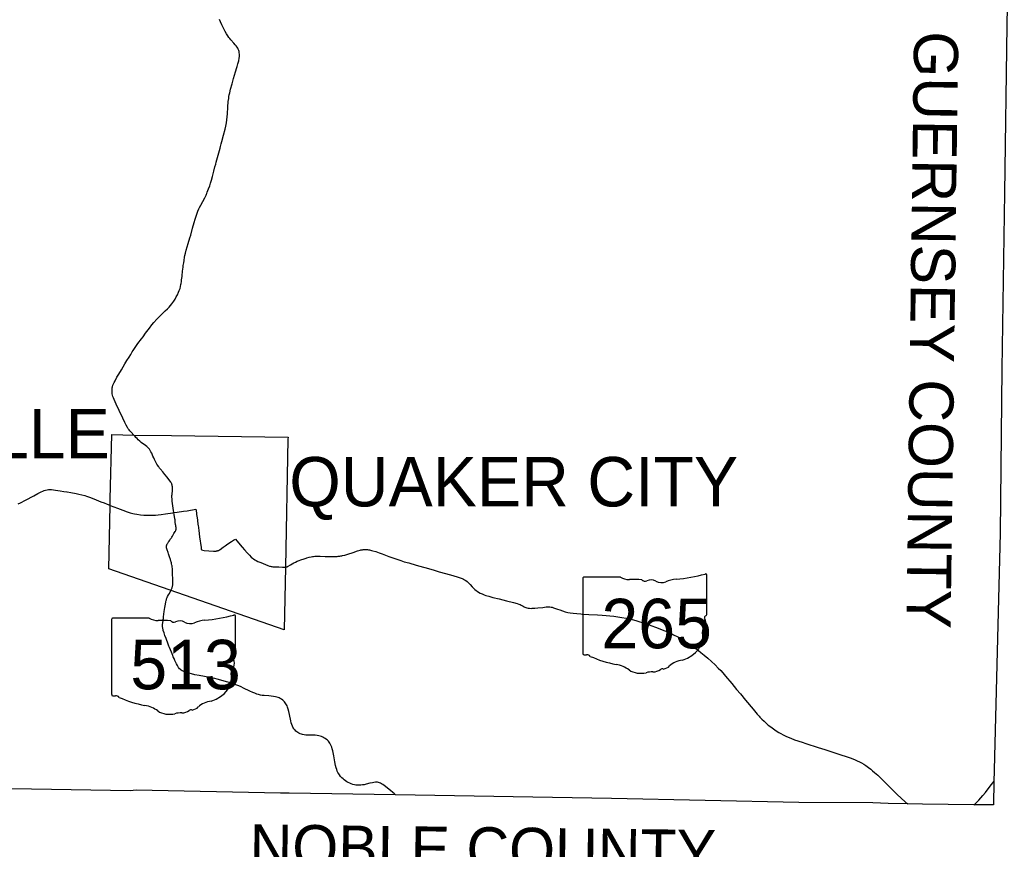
# Model space of a CAD drawing. Extents: x 2125567 to 2397567, y 653347 to 829347.
# Drawn here: x 2301307 to 2323667, y 712158 to 730931 of the extents above; entities that cross this region are included whole.
import ezdxf

# ---------------------------------------------------------------- set-up
doc = ezdxf.new("R2010")
doc.units = 0
for name, color, linetype in [('GM_X_Corporation', 7, 'Continuous'), ('GM_X_Corporation_Text', 7, 'Continuous'), ('GM_X_County', 7, 'Continuous'), ('GM_X_County_Text', 7, 'Continuous'), ('GM_X_State_Location', 7, 'Continuous'), ('GM_X_State_Route', 7, 'Continuous'), ('GM_X_State_Shield', 7, 'Continuous')]:
    doc.layers.add(name, color=color, linetype=linetype)

msp = doc.modelspace()

# ---------------------------------------------------------------- linework, layer by layer
at = {"layer": 'GM_X_Corporation'}
msp.add_lwpolyline([(2307286, 717126), (2303323, 718508), (2303355, 719937), (2303354, 720082), (2303390, 721541), (2303889, 721533), (2304739, 721520), (2307379, 721481), (2307373, 721436), (2307316, 718542)], close=True, dxfattribs=at)
at = {"layer": 'GM_X_County'}
msp.add_lwpolyline([(2323667, 732524), (2323636, 730805), (2323583, 727016), (2323525, 723028), (2323487, 719315), (2323348, 713955), (2323348, 713936), (2323344, 713702), (2323335, 713160), (2322891, 713164), (2321725, 713181), (2321394, 713182), (2320948, 713197), (2320605, 713210), (2318932, 713217), (2314694, 713310), (2309806, 713393), (2307398, 713424), (2307208, 713426), (2303943, 713494), (2303805, 713481), (2299787, 713549)], dxfattribs=at)
at = {"layer": 'GM_X_State_Route'}
msp.add_line((2305339, 719510), (2305342, 719489), dxfattribs=at)
for points in [[(2303890, 721530), (2303826, 721598), (2303799, 721627), (2303780, 721650), (2303763, 721674), (2303745, 721702), (2303716, 721754), (2303683, 721818), (2303635, 721915), (2303554, 722087), (2303488, 722230), (2303440, 722335), (2303425, 722371), (2303413, 722406), (2303405, 722438), (2303399, 722467), (2303396, 722500), (2303395, 722527), (2303396, 722560), (2303399, 722593), (2303401, 722603), (2303405, 722626), (2303414, 722658), (2303426, 722689), (2303439, 722719), (2303462, 722763), (2303505, 722840), (2303549, 722913), (2303609, 723011), (2303687, 723141), (2303733, 723216), (2303779, 723292), (2303819, 723359), (2303852, 723412), (2303873, 723445), (2303936, 723538), (2303981, 723602), (2304060, 723707), (2304097, 723757), (2304155, 723837), (2304243, 723955), (2304297, 724026), (2304341, 724079), (2304405, 724153), (2304446, 724196), (2304490, 724241), (2304597, 724342), (2304647, 724389), (2304684, 724427), (2304719, 724466), (2304748, 724501), (2304771, 724532), (2304792, 724562), (2304819, 724606), (2304848, 724657), (2304872, 724704), (2304899, 724763), (2304916, 724806), (2304932, 724852), (2304943, 724896), (2304952, 724937), (2304957, 724966), (2304963, 725005), (2304969, 725047), (2304974, 725086), (2304979, 725122), (2304984, 725164), (2304989, 725210), (2304992, 725236), (2304998, 725291), (2305002, 725324), (2305007, 725366), (2305017, 725428), (2305025, 725486), (2305036, 725561), (2305043, 725599), (2305054, 725647), (2305072, 725714), (2305118, 725868), (2305158, 725996), (2305176, 726059), (2305217, 726211), (2305256, 726344), (2305278, 726419), (2305304, 726507), (2305319, 726554), (2305336, 726600), (2305358, 726651), (2305373, 726683), (2305400, 726736), (2305446, 726819), (2305491, 726899), (2305523, 726963), (2305532, 726985), (2305538, 726999), (2305550, 727033), (2305579, 727103), (2305604, 727171), (2305624, 727233), (2305644, 727299), (2305666, 727384), (2305696, 727505), (2305723, 727603), (2305739, 727660), (2305752, 727711), (2305826, 727973), (2305841, 728026), (2305850, 728063), (2305865, 728127), (2305877, 728175), (2305916, 728318), (2305952, 728457), (2305967, 728521), (2305981, 728595), (2305992, 728666), (2306000, 728734), (2306006, 728806), (2306016, 728950), (2306025, 729084), (2306033, 729153), (2306038, 729192), (2306046, 729234), (2306056, 729279), (2306077, 729359), (2306112, 729485), (2306144, 729599), (2306166, 729677), (2306187, 729750), (2306194, 729772), (2306209, 729826), (2306222, 729873), (2306242, 729935), (2306260, 730005), (2306272, 730062), (2306277, 730098), (2306278, 730123), (2306277, 730136), (2306276, 730149), (2306273, 730181), (2306267, 730210), (2306259, 730238), (2306249, 730265), (2306237, 730288), (2306222, 730313), (2306204, 730340), (2306181, 730367), (2306149, 730404), (2306084, 730474), (2306059, 730504), (2306036, 730533), (2306012, 730568), (2305984, 730612), (2305954, 730664), (2305915, 730740), (2305877, 730820), (2305847, 730885), (2305826, 730937)], [(2304753, 720195), (2304756, 720217), (2304758, 720233), (2304759, 720247), (2304760, 720261), (2304762, 720279), (2304762, 720292), (2304763, 720310), (2304763, 720319), (2304763, 720331), (2304762, 720344), (2304762, 720352), (2304761, 720360), (2304761, 720365), (2304760, 720370), (2304759, 720374), (2304758, 720379), (2304757, 720387), (2304756, 720391), (2304755, 720396), (2304753, 720403), (2304753, 720407), (2304751, 720411), (2304750, 720415), (2304749, 720418), (2304748, 720422), (2304746, 720426), (2304738, 720444), (2304734, 720452), (2304725, 720469), (2304712, 720490), (2304682, 720530), (2304644, 720578), (2304591, 720641), (2304565, 720671), (2304542, 720698), (2304524, 720721), (2304511, 720736), (2304497, 720753), (2304487, 720765), (2304471, 720784), (2304451, 720810), (2304444, 720819), (2304428, 720843), (2304408, 720876), (2304400, 720891), (2304384, 720920), (2304369, 720952), (2304356, 720979), (2304339, 721013), (2304320, 721055), (2304310, 721079), (2304292, 721121), (2304274, 721156), (2304258, 721184), (2304239, 721211), (2304221, 721233), (2304203, 721251), (2304194, 721260), (2304180, 721272), (2304152, 721293), (2304120, 721315), (2304085, 721340), (2304057, 721362), (2304022, 721393), (2303989, 721425), (2303961, 721453), (2303936, 721479), (2303914, 721503), (2303890, 721530)], [(2301270, 719974), (2301323, 720001), (2301435, 720062), (2301622, 720158), (2301715, 720207), (2301793, 720247), (2301826, 720263), (2301856, 720274), (2301890, 720285), (2301928, 720294), (2301957, 720298), (2301979, 720299), (2302025, 720298), (2302074, 720293), (2302116, 720288), (2302221, 720271), (2302301, 720257), (2302373, 720245)], [(2302373, 720245), (2302379, 720244), (2302466, 720230), (2302586, 720209), (2302644, 720198), (2302714, 720181), (2302777, 720163), (2302817, 720151), (2302885, 720126), (2302986, 720087), (2303144, 720024), (2303214, 719997), (2303281, 719970), (2303343, 719944), (2303351, 719941)], [(2304753, 720086), (2304752, 720091), (2304751, 720100), (2304750, 720112), (2304750, 720124), (2304749, 720135), (2304749, 720146), (2304750, 720156), (2304750, 720162), (2304750, 720168), (2304751, 720179), (2304753, 720195)], [(2304832, 719511), (2304825, 719559), (2304819, 719611), (2304815, 719633), (2304801, 719731), (2304795, 719778), (2304787, 719828), (2304780, 719880), (2304758, 720039), (2304753, 720086)], [(2303351, 719941), (2303518, 719874), (2303638, 719830), (2303738, 719796), (2303807, 719774), (2303864, 719759), (2303906, 719750), (2303954, 719741), (2304042, 719729), (2304114, 719721), (2304177, 719718), (2304243, 719716), (2304264, 719717)], [(2304264, 719717), (2304308, 719717), (2304377, 719721), (2304440, 719727), (2304508, 719736), (2304605, 719750), (2304771, 719774), (2304795, 719778)], [(2304795, 719778), (2304865, 719785), (2305011, 719807), (2305092, 719818), (2305292, 719853)], [(2305292, 719853), (2305302, 719774), (2305308, 719733), (2305318, 719662), (2305326, 719604), (2305339, 719510)], [(2304684, 719133), (2304699, 719155), (2304717, 719182), (2304736, 719209), (2304746, 719224), (2304760, 719246), (2304778, 719274), (2304795, 719302), (2304822, 719346), (2304829, 719358), (2304834, 719369), (2304837, 719378), (2304840, 719386), (2304842, 719398), (2304843, 719406), (2304843, 719414), (2304843, 719418), (2304843, 719427), (2304842, 719440), (2304839, 719463), (2304836, 719485), (2304832, 719511)], [(2305342, 719489), (2305357, 719373), (2305376, 719230), (2305407, 718989), (2305408, 718982), (2305409, 718976), (2305410, 718968)], [(2304726, 718012), (2304742, 718047), (2304748, 718062), (2304752, 718075), (2304756, 718088), (2304760, 718102), (2304764, 718119), (2304767, 718137), (2304768, 718154), (2304769, 718169), (2304770, 718188), (2304770, 718205), (2304768, 718286), (2304764, 718378), (2304762, 718469), (2304759, 718512), (2304755, 718544), (2304751, 718572), (2304748, 718589), (2304743, 718618), (2304740, 718636), (2304737, 718646), (2304735, 718655), (2304734, 718661), (2304732, 718666), (2304727, 718680), (2304714, 718717), (2304693, 718779), (2304680, 718819), (2304672, 718844), (2304661, 718875), (2304654, 718896), (2304649, 718909), (2304633, 718956), (2304631, 718964), (2304629, 718972), (2304627, 718981), (2304626, 718991), (2304625, 718998), (2304625, 719005), (2304625, 719012), (2304625, 719019), (2304627, 719026), (2304630, 719035), (2304632, 719043), (2304637, 719053), (2304642, 719064), (2304647, 719075), (2304654, 719087), (2304662, 719101), (2304681, 719129), (2304684, 719133)], [(2305418, 718931), (2305479, 718921), (2305581, 718913), (2305689, 718906), (2305719, 718905), (2305732, 718906), (2305747, 718908), (2305760, 718910), (2305772, 718912), (2305781, 718915), (2305788, 718917), (2305797, 718920), (2305805, 718923), (2305825, 718934), (2305838, 718943), (2305908, 718992), (2305956, 719027), (2306017, 719071), (2306096, 719124), (2306140, 719152), (2306184, 719179)], [(2306184, 719179), (2306219, 719138), (2306341, 718997), (2306393, 718938), (2306453, 718869), (2306504, 718810), (2306542, 718771), (2306569, 718747), (2306594, 718728), (2306624, 718709), (2306658, 718690), (2306696, 718672), (2306759, 718645), (2306868, 718600), (2306919, 718579), (2306956, 718567), (2306973, 718563), (2306993, 718558), (2307012, 718555), (2307032, 718552), (2307056, 718550), (2307080, 718549), (2307165, 718546), (2307247, 718544), (2307289, 718544), (2307305, 718544), (2307312, 718544)], [(2305410, 718968), (2305412, 718958), (2305413, 718952), (2305415, 718942), (2305418, 718931)], [(2307312, 718544), (2307319, 718545), (2307330, 718546), (2307343, 718548), (2307354, 718552), (2307364, 718556), (2307373, 718560), (2307380, 718564), (2307434, 718596), (2307506, 718637), (2307541, 718655), (2307585, 718676), (2307625, 718692), (2307668, 718708), (2307737, 718730), (2307784, 718745), (2307799, 718750), (2307852, 718765), (2307900, 718778), (2307928, 718784), (2307955, 718787), (2307983, 718790), (2308014, 718791), (2308100, 718790), (2308212, 718787), (2308244, 718786), (2308303, 718785), (2308421, 718785), (2308486, 718787), (2308507, 718788), (2308528, 718790), (2308546, 718792), (2308570, 718796), (2308591, 718800), (2308611, 718804), (2308659, 718817), (2308731, 718838), (2308849, 718877), (2308949, 718909), (2309006, 718926), (2309026, 718931), (2309045, 718935), (2309059, 718938), (2309074, 718940), (2309085, 718942), (2309097, 718943), (2309112, 718944), (2309127, 718944), (2309139, 718944), (2309157, 718943), (2309173, 718941), (2309193, 718938), (2309217, 718933), (2309242, 718927), (2309266, 718922), (2309293, 718914), (2309362, 718894), (2309440, 718868), (2309505, 718844), (2309659, 718787), (2309680, 718779), (2309813, 718731), (2309930, 718690), (2310005, 718666), (2310106, 718637), (2310273, 718590), (2310440, 718541), (2310469, 718533), (2310658, 718479), (2310797, 718439), (2311048, 718365), (2311200, 718321), (2311269, 718299), (2311315, 718282), (2311346, 718269), (2311369, 718257), (2311395, 718242), (2311424, 718220), (2311454, 718193), (2311494, 718149), (2311538, 718100), (2311569, 718067), (2311603, 718036), (2311633, 718011), (2311651, 717998), (2311681, 717979), (2311721, 717957), (2311766, 717936), (2311811, 717918), (2311851, 717904), (2311917, 717884), (2312012, 717858), (2312155, 717823), (2312321, 717781), (2312473, 717741), (2312559, 717717), (2312596, 717706), (2312624, 717695), (2312651, 717682), (2312697, 717657), (2312719, 717645)], [(2309751, 713435), (2309743, 713441), (2309690, 713485), (2309628, 713539), (2309581, 713580), (2309550, 713604), (2309521, 713624), (2309493, 713641), (2309467, 713654), (2309443, 713664), (2309419, 713670), (2309396, 713673), (2309377, 713675), (2309351, 713674), (2309319, 713670), (2309284, 713664), (2309227, 713650), (2309144, 713629), (2309099, 713619), (2309057, 713613), (2309020, 713609), (2308987, 713608), (2308948, 713609), (2308912, 713612), (2308879, 713617), (2308840, 713626), (2308806, 713637), (2308772, 713651), (2308739, 713666), (2308708, 713684), (2308674, 713706), (2308645, 713728), (2308620, 713749), (2308592, 713777), (2308566, 713807), (2308540, 713840), (2308521, 713868), (2308505, 713896), (2308490, 713926), (2308476, 713963), (2308464, 714001), (2308452, 714052), (2308434, 714139), (2308409, 714271), (2308387, 714383), (2308375, 714431), (2308363, 714468), (2308350, 714501), (2308336, 714531), (2308320, 714559), (2308306, 714580), (2308289, 714601), (2308267, 714624), (2308243, 714645), (2308217, 714664), (2308189, 714682), (2308161, 714697), (2308134, 714709), (2308104, 714720), (2308072, 714728), (2308037, 714733), (2307992, 714737), (2307903, 714740), (2307808, 714741), (2307775, 714743), (2307739, 714748), (2307706, 714754), (2307678, 714762), (2307650, 714772), (2307620, 714786), (2307597, 714799), (2307575, 714814), (2307554, 714831), (2307535, 714850), (2307518, 714871), (2307501, 714895), (2307486, 714921), (2307474, 714945), (2307460, 714979), (2307449, 715017), (2307438, 715062), (2307410, 715206), (2307394, 715273), (2307380, 715327), (2307367, 715371), (2307355, 715401), (2307342, 715427), (2307328, 715452), (2307313, 715474), (2307297, 715494), (2307276, 715514), (2307255, 715533), (2307228, 715552), (2307195, 715572), (2307173, 715584), (2307152, 715593), (2307125, 715601), (2307090, 715610), (2307049, 715617), (2306997, 715623), (2306942, 715627), (2306838, 715635), (2306789, 715641), (2306750, 715647), (2306708, 715657), (2306667, 715669), (2306621, 715687), (2306576, 715706), (2306508, 715739), (2306370, 715807), (2306317, 715832), (2306260, 715856), (2306193, 715882), (2306140, 715901), (2306078, 715921), (2305984, 715950), (2305858, 715985), (2305773, 716008), (2305719, 716021), (2305606, 716043), (2305364, 716088), (2305268, 716107), (2305191, 716125), (2305131, 716141), (2305080, 716157), (2305046, 716169), (2305003, 716186), (2304983, 716197), (2304957, 716213), (2304941, 716225), (2304922, 716243), (2304899, 716271), (2304890, 716285), (2304872, 716317), (2304851, 716357), (2304817, 716432), (2304797, 716474), (2304780, 716512), (2304767, 716541), (2304736, 716619), (2304714, 716673), (2304695, 716722), (2304683, 716753), (2304666, 716799), (2304616, 716927), (2304590, 716998), (2304571, 717054), (2304553, 717110), (2304548, 717129), (2304545, 717145), (2304542, 717159), (2304540, 717172), (2304539, 717186), (2304538, 717202), (2304538, 717212), (2304538, 717225), (2304539, 717236), (2304539, 717248), (2304549, 717326), (2304552, 717354), (2304555, 717378), (2304557, 717397), (2304560, 717420), (2304576, 717540), (2304590, 717629), (2304602, 717704), (2304611, 717755), (2304619, 717790), (2304623, 717806), (2304629, 717825), (2304635, 717841), (2304641, 717856), (2304652, 717880), (2304672, 717916), (2304691, 717949), (2304726, 718012)], [(2312719, 717645), (2312729, 717640), (2312753, 717629), (2312780, 717620), (2312808, 717614), (2312840, 717611), (2312882, 717610), (2312895, 717611), (2312931, 717613), (2312957, 717615), (2313029, 717621), (2313140, 717632), (2313211, 717641), (2313251, 717644), (2313277, 717645), (2313297, 717643), (2313331, 717638)], [(2313331, 717638), (2313347, 717635), (2313362, 717631), (2313379, 717625), (2313468, 717593), (2313524, 717573), (2313586, 717551), (2313645, 717532), (2313703, 717518), (2313761, 717507), (2313826, 717498), (2313905, 717491), (2313997, 717484), (2314026, 717482), (2314177, 717472), (2314377, 717461), (2314478, 717454), (2314742, 717430), (2314833, 717419), (2314924, 717405), (2315021, 717388), (2315101, 717371), (2315158, 717357), (2315240, 717334), (2315334, 717306), (2315440, 717272), (2315546, 717235), (2315746, 717162), (2315878, 717112), (2315941, 717086), (2316016, 717053), (2316095, 717014), (2316192, 716965), (2316252, 716932), (2316319, 716891), (2316391, 716845), (2316470, 716792), (2316598, 716701), (2316662, 716655), (2316716, 716613), (2316787, 716554), (2316874, 716480), (2316954, 716407), (2317038, 716329), (2317108, 716260), (2317165, 716201), (2317209, 716152), (2317275, 716075), (2317416, 715907), (2317523, 715776)], [(2317523, 715776), (2317607, 715673), (2317726, 715529), (2317894, 715327), (2317987, 715217), (2318031, 715169), (2318047, 715151), (2318096, 715099), (2318143, 715053), (2318189, 715011), (2318240, 714968), (2318294, 714926), (2318356, 714882), (2318418, 714839), (2318477, 714803), (2318522, 714776), (2318578, 714747), (2318637, 714718), (2318691, 714694), (2318749, 714670), (2318835, 714638), (2319005, 714579), (2319089, 714551), (2319368, 714463), (2319521, 714414), (2319696, 714358), (2319855, 714305), (2320022, 714249), (2320115, 714216), (2320167, 714195), (2320191, 714186), (2320251, 714160), (2320305, 714135), (2320351, 714111), (2320398, 714083), (2320447, 714050), (2320509, 714006), (2320556, 713971), (2320599, 713936), (2320644, 713898), (2320715, 713831), (2320901, 713650), (2321012, 713539), (2321146, 713408), (2321252, 713305), (2321325, 713239), (2321395, 713179)], [(2322892, 713162), (2322910, 713178), (2322963, 713228), (2323000, 713265), (2323049, 713319), (2323093, 713372), (2323149, 713441), (2323259, 713588), (2323345, 713699)], [(2309807, 713391), (2309777, 713416), (2309751, 713435)]]:
    msp.add_lwpolyline(points, dxfattribs=at)
at = {"layer": 'GM_X_State_Shield'}
for p, q in [((2314047, 718288), (2314047, 716587)), ((2314895, 718317), (2314074, 718317)), ((2316848, 717469), (2316848, 718359)), ((2303386, 717360), (2303386, 715659)), ((2304234, 717389), (2303414, 717389)), ((2306188, 716541), (2306188, 717431)), ((2316848, 717469), (2316848, 717469)), ((2306188, 716541), (2306188, 716541))]:
    msp.add_line(p, q, dxfattribs=at)
for centre, major_axis, start_param, end_param in [((2314079, 718291), (32.5, 0), 1.712693, 3.28349), ((2315090, 718514), (315, 0), 4.042523, 4.731795), ((2315195, 717362), (1130, 0), 1.404758, 1.657858), ((2315451, 718300), (90.8, 0), 3.836095, 5.185415), ((2315584, 718104), (189, 0), 0.950623, 2.079405), ((2315828, 718373), (227, 0), 4.081561, 5.145723), ((2316229, 717797), (598, 0), 1.699011, 2.107814), ((2315850, 720636), (2971, 0), 4.814394, 5.042369), ((2316817, 718363), (31.2, 0), 6.141152, 7.989035), ((2303418, 717363), (32.5, 0), 1.712693, 3.28349), ((2304430, 717586), (315, 0), 4.042523, 4.731795), ((2304534, 716434), (1130, 0), 1.404758, 1.657858), ((2304791, 717372), (90.8, 0), 3.836095, 5.185415), ((2304924, 717176), (189, 0), 0.950623, 2.079405), ((2305168, 717445), (227, 0), 4.081561, 5.145723), ((2305569, 716869), (598, 0), 1.699011, 2.107814), ((2305190, 719708), (2971, 0), 4.814394, 5.042369), ((2306157, 717435), (31.2, 0), 6.141152, 7.989035), ((2316841, 717404), (48.3, 0), 1.883978, 3.671073), ((2316534, 717291), (290, 0), 5.934695, 6.695948), ((2316815, 717466), (33.4, 0), 5.05454, 6.418171), ((2316017, 716984), (743, 0), 5.101752, 6.440018), ((2316960, 717097), (211, 0), 2.387724, 3.262537), ((2306181, 716476), (48.3, 0), 1.883978, 3.671073), ((2305874, 716363), (290, 0), 5.934695, 6.695948), ((2306155, 716538), (33.4, 0), 5.05454, 6.418171), ((2314079, 716583), (32.7, 0), 3.00124, 4.508301), ((2314084, 716757), (250, 0), 4.665946, 4.897461), ((2314135, 716488), (90.1, 0), 0.519207, 1.627899), ((2315273, 718017), (2146, 0), 4.195997, 4.488961), ((2316330, 716109), (407, 0), 1.647645, 2.488434), ((2306300, 716169), (211, 0), 2.387724, 3.262537), ((2314633, 715822), (671, 0), 0.823519, 1.323587), ((2315359, 716480), (426, 0), 4.026481, 4.996735), ((2315605, 715892), (350, 0), 1.495662, 1.94098), ((2315636, 716353), (227, 0), 4.691044, 5.507374), ((2315842, 716188), (63.9, 0), 1.147584, 2.315152), ((2315815, 716422), (240, 0), 4.937069, 5.64225), ((2305357, 716056), (743, 0), 5.101752, 6.440018), ((2303419, 715655), (32.7, 0), 3.00124, 4.508301), ((2303424, 715829), (250, 0), 4.665946, 4.897461), ((2303475, 715560), (90.1, 0), 0.519207, 1.627899), ((2304612, 717089), (2146, 0), 4.195997, 4.488961), ((2305670, 715181), (407, 0), 1.647645, 2.488434), ((2303973, 714894), (671, 0), 0.823519, 1.323587), ((2304699, 715552), (426, 0), 4.026481, 4.996735), ((2304976, 715425), (227, 0), 4.691044, 5.507374), ((2305181, 715260), (63.9, 0), 1.147584, 2.315152), ((2305154, 715494), (240, 0), 4.937069, 5.64225), ((2304945, 714964), (350, 0), 1.495662, 1.94098)]:
    msp.add_ellipse(centre, major_axis=major_axis, ratio=0.8, start_param=start_param, end_param=end_param, dxfattribs=at)

# ---------------------------------------------------------------- texts
at = {"layer": 'GM_X_Corporation_Text'}
for s, p in [('SALESVILLE', (2294435, 721005)), ('QUAKER CITY', (2307404, 719916))]:
    msp.add_text(s, height=1120, rotation=0, dxfattribs=at).set_placement(p)
at = {"layer": 'GM_X_County_Text'}
for s, rotation, p in [('GUERNSEY COUNTY', 269.2603, (2321538, 730675)), ('NOBLE COUNTY', 359.2846, (2306500, 711723))]:
    msp.add_text(s, height=1000, rotation=rotation, dxfattribs=at).set_placement(p)
at = {"layer": 'GM_X_State_Location'}
for s, p in [('513', (2304147, 717096)), ('265', (2314971, 717123))]:
    msp.add_text(s, height=1, rotation=0, dxfattribs=at).set_placement(p)
for s, p in [('s', (2304500, 717169)), ('r', (2304500, 717169)), ('s', (2315324, 717195)), ('r', (2315324, 717195))]:
    msp.add_text(s, height=1, dxfattribs=at).set_placement(p)
at = {"layer": 'GM_X_State_Shield'}
for s, p in [('265', (2314464, 716706)), ('513', (2303807, 715778))]:
    msp.add_text(s, height=1120.7, dxfattribs=at).set_placement(p)

doc.saveas('drawing.dxf')
